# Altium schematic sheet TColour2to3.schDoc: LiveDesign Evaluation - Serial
size A3; Organization: Altium Limited; Address1: L3, 12a Rodborough Rd; Address2: Frenchs Forest; Address3: NSW; Address4: Australia 2086; DocumentNumber: 6; SheetNumber: 6; SheetTotal: 7
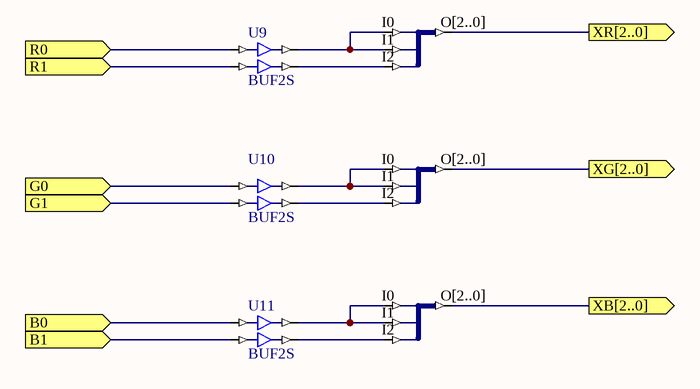
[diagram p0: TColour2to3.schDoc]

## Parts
IC18  J3S_3B  (value not drawn)
IC19  J3S_3B  (value not drawn)
IC20  J3S_3B  (value not drawn)
U9  BUF2S
U10  BUF2S
U11  BUF2S

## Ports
B0 (in), B1 (in), G0 (in), G1 (in), R0 (in), R1 (in), XB[2..0] (out), XG[2..0] (out), XR[2..0] (out)

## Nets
B0: U11.I0 ; port B0
B1: U11.I1 ; port B1
G0: U10.I0 ; port G0
G1: U10.I1 ; port G1
R0: U9.I0 ; port R0
R1: U9.I1 ; port R1
NetIC18_I0: IC18.I0 IC18.I1 U9.O0
NetIC18_I2: IC18.I2 U9.O1
NetIC19_I0: IC19.I0 IC19.I1 U10.O0
NetIC19_I2: IC19.I2 U10.O1
NetIC20_I0: IC20.I0 IC20.I1 U11.O0
NetIC20_I2: IC20.I2 U11.O1

Not connected (* = marked no-connect by the designer): IC18 O[2..0]; IC19 O[2..0]; IC20 O[2..0]

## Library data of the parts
IC18-IC20 = J3S_3B: 3 Single pin inputs to single 3-Bit output bus; ArchiveName: GENERIC; VHDLIB_SIM: GENERIC_LIB
U9-U11 = BUF2S: 2-Bit General Purpose (Non-inverting) Buffer, Single Pin Version; ArchiveName: GENERIC; VHDLIB_SIM: GENERIC_LIB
